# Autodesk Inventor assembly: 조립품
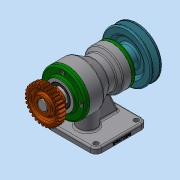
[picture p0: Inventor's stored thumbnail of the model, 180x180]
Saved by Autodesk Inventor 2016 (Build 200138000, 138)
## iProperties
Created: 2019-01
Part Number: 조립품
Material: 일반
Document SubType Name: Assembly
Designer: Administrator
Author: Administrator
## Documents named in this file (15)
- C:\Users\Administrator\Desktop\490108V1015\조립품.iam
- C:\Users\Administrator\Desktop\490108V1015\본체.ipt
- C:\Users\Administrator\Desktop\490108V1015\앞커버.ipt
- C:\Users\Administrator\Desktop\490108V1015\뒤커버.ipt
- C:\Users\Administrator\Desktop\490108V1015\볼트 M4.ipt
- C:\Users\Administrator\Desktop\490108V1015\베어링 6205.ipt
- C:\Users\Administrator\Desktop\490108V1015\베어링 6203.ipt
- C:\Users\Administrator\Desktop\490108V1015\축.ipt
- C:\Users\Administrator\Desktop\490108V1015\오일 실 17 30 8.ipt
- C:\Users\Administrator\Desktop\490108V1015\오일 실 25 38 8.ipt
- C:\Users\Administrator\Desktop\490108V1015\키 5 x 5 x 20.ipt
- C:\Users\Administrator\Desktop\490108V1015\키 6 x 6 x 18.ipt
- C:\Users\Administrator\Desktop\490108V1015\스퍼기어.ipt
- C:\Users\Administrator\Desktop\490108V1015\V-벨트풀리.ipt
- C:\Users\Administrator\Desktop\490108V1015\멈춤나사 M3.ipt
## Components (1 placed, 1 different names)
1. V-벨트풀리:1 — 각도:5
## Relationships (1: Angle 1)
- 각도:5 [Angle]: V-벨트풀리:1
